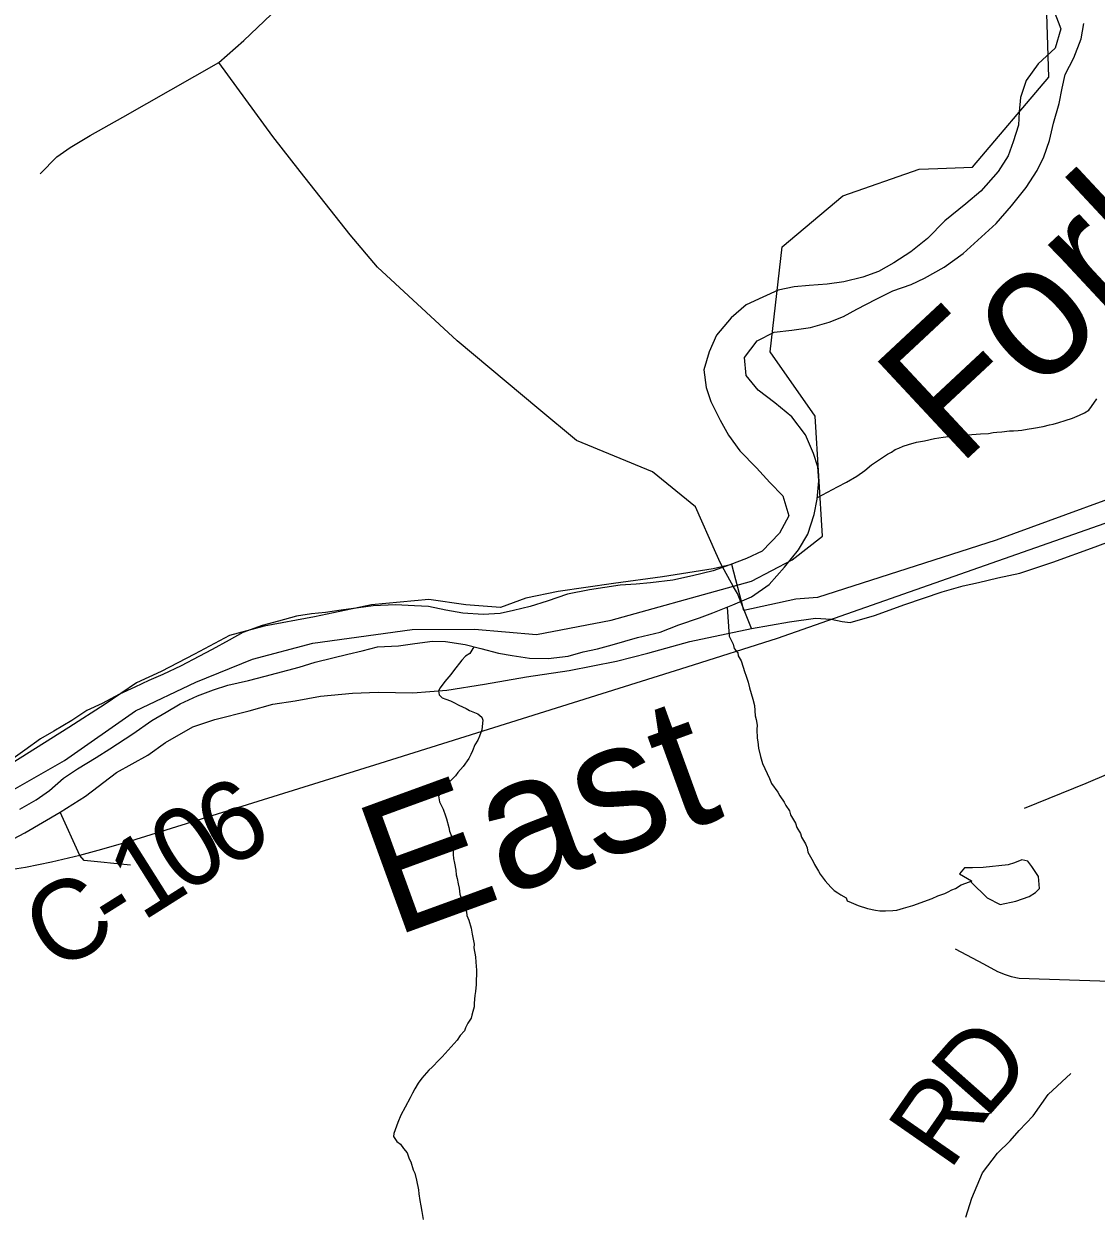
# Model space of a CAD drawing. Extents: x 0 to 34, y 0 to 22.
# Drawn here: x 6.1496 to 6.5335, y 18.3763 to 18.803 of the extents above; entities that cross this region are included whole.
import ezdxf

# ---------------------------------------------------------------- set-up
doc = ezdxf.new("R2010")
doc.units = 0
for name, color, linetype in [('GM_X_City_Street', 7, 'Continuous'), ('GM_X_Corporation', 7, 'Continuous'), ('GM_X_County_Road', 7, 'Continuous'), ('GM_X_County_Road_Text', 7, 'Continuous'), ('GM_X_Major_River', 7, 'Continuous'), ('GM_X_Major_River_Text', 7, 'Continuous'), ('GM_X_Minor_Lake', 7, 'Continuous'), ('GM_X_Minor_River', 7, 'Continuous'), ('GM_X_Rail_Line', 7, 'Continuous'), ('GM_X_Township', 7, 'Continuous'), ('GM_X_Township_Road', 7, 'Continuous'), ('GM_X_Township_Road_Text', 7, 'Continuous')]:
    doc.layers.add(name, color=color, linetype=linetype)

msp = doc.modelspace()

# ---------------------------------------------------------------- linework, layer by layer
at = {"layer": 'GM_X_City_Street'}
msp.add_lwpolyline([(6.15544, 18.74932), (6.16151, 18.7554), (6.16624, 18.75877), (6.17338, 18.76308), (6.18512, 18.76956), (6.21944, 18.7891)], dxfattribs=at)
at = {"layer": 'GM_X_Corporation'}
for points in [[(6.14063, 18.52601), (6.16415, 18.53935), (6.18957, 18.55715), (6.21118, 18.56732), (6.23152, 18.57559), (6.25312, 18.58131), (6.28865, 18.58623), (6.31096, 18.58639), (6.3332, 18.58449), (6.35989, 18.58957), (6.40364, 18.60179), (6.4101, 18.60356), (6.42472, 18.61118), (6.4355, 18.61968), (6.4329, 18.66259), (6.41682, 18.68566), (6.4211, 18.7232), (6.44286, 18.74144), (6.47015, 18.75104), (6.47689, 18.75126), (6.48931, 18.75167), (6.51663, 18.78387), (6.51458, 18.8485)], [(6.5611, 18.64133), (6.49767, 18.61824), (6.43381, 18.59772), (6.42603, 18.59709), (6.40738, 18.59304), (6.40313, 18.60945), (6.39637, 18.6079), (6.3783, 18.60505), (6.3607, 18.60268), (6.34097, 18.59987), (6.32932, 18.59744), (6.32028, 18.59411), (6.30792, 18.59506), (6.2946, 18.59697), (6.27416, 18.59506), (6.25371, 18.59078), (6.23564, 18.58745), (6.22327, 18.58413), (6.21071, 18.57738), (6.19878, 18.57116), (6.18999, 18.56712), (6.17881, 18.55951), (6.16573, 18.55118), (6.14505, 18.53811)]]:
    msp.add_lwpolyline(points, dxfattribs=at)
at = {"layer": 'GM_X_County_Road'}
for points in [[(6.33404, 18.66506), (6.30473, 18.68949), (6.27628, 18.7159), (6.26647, 18.7275), (6.24855, 18.75009), (6.23876, 18.76263), (6.21944, 18.7891), (6.22844, 18.797), (6.25779, 18.82504)], [(6.39742, 18.61361), (6.39013, 18.63016), (6.37464, 18.64263), (6.34754, 18.65381), (6.33404, 18.66506)], [(6.41016, 18.58664), (6.42376, 18.58898), (6.43302, 18.59026), (6.43862, 18.5899), (6.44255, 18.58905), (6.44546, 18.5887), (6.4542, 18.59119), (6.46507, 18.59513), (6.47843, 18.59975), (6.48588, 18.60181), (6.49135, 18.60309), (6.49838, 18.60472), (6.50626, 18.60643), (6.51807, 18.61036), (6.53322, 18.61584), (6.56259, 18.62681)], [(6.40444, 18.6003), (6.40375, 18.60153), (6.39904, 18.60994), (6.39742, 18.61361)], [(6.41016, 18.58664), (6.40513, 18.59908), (6.40444, 18.6003)], [(6.13972, 18.50806), (6.15002, 18.51339), (6.16267, 18.5208), (6.1717, 18.52658), (6.18282, 18.53505), (6.19402, 18.54122), (6.20034, 18.54574), (6.2101, 18.55134), (6.21805, 18.55405), (6.23034, 18.55712), (6.23883, 18.55947), (6.24679, 18.56073), (6.25585, 18.56236), (6.26724, 18.56346), (6.27653, 18.56384), (6.28892, 18.56353), (6.30108, 18.56454), (6.3146, 18.56671), (6.32961, 18.56928), (6.34488, 18.5716), (6.36179, 18.57492), (6.37298, 18.57772), (6.38806, 18.58187), (6.41016, 18.58664)]]:
    msp.add_lwpolyline(points, dxfattribs=at)
at = {"layer": 'GM_X_Major_River'}
for points in [[(6.51836, 18.80776), (6.52087, 18.80124), (6.51882, 18.79425), (6.51282, 18.78867), (6.50851, 18.78267), (6.50648, 18.77663), (6.50599, 18.7715), (6.50569, 18.76676), (6.50385, 18.76071), (6.50204, 18.7558), (6.4985, 18.75017), (6.49227, 18.74307), (6.48685, 18.73862), (6.47932, 18.7325), (6.47311, 18.72616), (6.46712, 18.72134), (6.46115, 18.71747), (6.45557, 18.71435), (6.45003, 18.71237), (6.44315, 18.71061), (6.43725, 18.70978), (6.43079, 18.70934), (6.42546, 18.70888), (6.41974, 18.70767), (6.41418, 18.70512), (6.40824, 18.70239), (6.40282, 18.69775), (6.39756, 18.69158), (6.39496, 18.68555), (6.39311, 18.67912), (6.39393, 18.67283), (6.39553, 18.66785), (6.39898, 18.66113), (6.4019, 18.65574), (6.40596, 18.65014), (6.4119, 18.64413), (6.41672, 18.63889), (6.42136, 18.63404), (6.42348, 18.62696), (6.42012, 18.62076), (6.4139, 18.61423), (6.40834, 18.61168), (6.40241, 18.60933), (6.39647, 18.60717), (6.38903, 18.60542), (6.38198, 18.60386), (6.37398, 18.60288), (6.36885, 18.60241), (6.36315, 18.60215), (6.3521, 18.60048)], [(6.51823, 18.76745), (6.52029, 18.77444), (6.52136, 18.77993), (6.52241, 18.78486), (6.52558, 18.79088), (6.5282, 18.79767), (6.52908, 18.80317)], [(6.14823, 18.52194), (6.154, 18.52525), (6.15882, 18.52857), (6.16385, 18.53303), (6.16886, 18.53635), (6.17559, 18.5404), (6.18041, 18.54353), (6.18868, 18.54888), (6.19543, 18.55368), (6.20062, 18.55662), (6.20562, 18.55956), (6.21176, 18.56248), (6.2175, 18.56464), (6.22266, 18.56625), (6.2301, 18.56799), (6.23602, 18.56958), (6.24824, 18.57275), (6.25397, 18.57454), (6.26027, 18.57612), (6.26561, 18.57734), (6.27076, 18.57857), (6.2763, 18.57998), (6.28371, 18.58039), (6.28961, 18.58122), (6.29589, 18.58204), (6.30064, 18.58195), (6.30764, 18.58085), (6.3133, 18.5794), (6.31953, 18.57775), (6.32444, 18.57689), (6.33069, 18.576), (6.33733, 18.57587), (6.34456, 18.57667), (6.34991, 18.57827), (6.35506, 18.57931), (6.36021, 18.58072), (6.36938, 18.58339), (6.37739, 18.58531), (6.38409, 18.58784), (6.39155, 18.59035), (6.39634, 18.59215), (6.40342, 18.59505), (6.41013, 18.59795), (6.41649, 18.60238), (6.42194, 18.60855), (6.42701, 18.61472), (6.43036, 18.62036), (6.4326, 18.62735), (6.43367, 18.63284), (6.4342, 18.63948), (6.43392, 18.64443), (6.43232, 18.64922), (6.42943, 18.65593), (6.42463, 18.66231), (6.41848, 18.66738), (6.41251, 18.67188), (6.40825, 18.6771), (6.40764, 18.68358), (6.41214, 18.68957), (6.41828, 18.69268), (6.42455, 18.69331), (6.43122, 18.69431), (6.43791, 18.69627), (6.44307, 18.69825), (6.44788, 18.70082), (6.45479, 18.70448), (6.46074, 18.7074), (6.46724, 18.70974), (6.47203, 18.71192), (6.47915, 18.71596), (6.48589, 18.72076), (6.49248, 18.72671), (6.49771, 18.73155), (6.50316, 18.7379), (6.50843, 18.74445), (6.51236, 18.75045), (6.51474, 18.75535), (6.51677, 18.7612), (6.51823, 18.76745)], [(6.3521, 18.60048), (6.34429, 18.59892), (6.33702, 18.59641), (6.3309, 18.59445), (6.32499, 18.59305), (6.32022, 18.592), (6.31413, 18.59156), (6.30674, 18.59209), (6.30069, 18.59317), (6.29446, 18.59443), (6.28953, 18.59473), (6.2827, 18.59506), (6.27472, 18.59465), (6.26939, 18.594), (6.2633, 18.59317), (6.25759, 18.59234), (6.25264, 18.59187), (6.24731, 18.59103), (6.24082, 18.58926), (6.2349, 18.58767), (6.22801, 18.58515), (6.2232, 18.5824), (6.21706, 18.5791), (6.21226, 18.57654), (6.20592, 18.57324), (6.1994, 18.57015), (6.19442, 18.56797), (6.18943, 18.5656), (6.18387, 18.56305), (6.17772, 18.55975), (6.17216, 18.5572), (6.16677, 18.5537), (6.16042, 18.54984), (6.15562, 18.54708), (6.15002, 18.54302), (6.14501, 18.53951)]]:
    msp.add_lwpolyline(points, dxfattribs=at)
at = {"layer": 'GM_X_Minor_Lake'}
msp.add_lwpolyline([(6.48886, 18.49632), (6.48874, 18.4958), (6.49451, 18.49017), (6.49921, 18.48779), (6.50475, 18.48901), (6.50953, 18.49062), (6.51184, 18.49209), (6.5132, 18.49358), (6.51291, 18.49777), (6.51052, 18.50143), (6.50904, 18.50336), (6.50695, 18.50378), (6.50427, 18.5027), (6.50198, 18.50199)], dxfattribs=at)
at = {"layer": 'GM_X_Minor_River'}
for points in [[(6.43372, 18.63349), (6.4409, 18.63731), (6.44417, 18.63893), (6.44783, 18.64111), (6.45073, 18.64313), (6.45306, 18.64515), (6.45557, 18.64679), (6.45886, 18.64898), (6.46021, 18.64971), (6.46156, 18.65062), (6.4629, 18.65115), (6.46444, 18.65187), (6.46635, 18.65239), (6.46922, 18.65327), (6.47208, 18.65376), (6.47571, 18.65461), (6.47876, 18.6551), (6.48162, 18.65541), (6.48276, 18.65557), (6.48619, 18.65586), (6.48904, 18.65597), (6.49209, 18.65627), (6.49494, 18.65639), (6.49666, 18.65672), (6.49799, 18.65688), (6.4997, 18.65702), (6.50256, 18.65732), (6.50389, 18.65729), (6.5056, 18.65743), (6.50693, 18.65759), (6.50884, 18.65792), (6.51113, 18.65824), (6.51456, 18.65891), (6.51686, 18.65942), (6.51819, 18.65976), (6.52011, 18.66028), (6.5224, 18.66098), (6.52508, 18.66186), (6.52758, 18.66293), (6.52931, 18.66383), (6.53086, 18.66474), (6.53184, 18.66604), (6.53381, 18.66884)], [(6.40143, 18.59423), (6.40213, 18.58388), (6.40357, 18.581), (6.40392, 18.57947), (6.40521, 18.57792), (6.40537, 18.57678), (6.40646, 18.57504), (6.40716, 18.57275), (6.40769, 18.57122), (6.40822, 18.5695), (6.40893, 18.56739), (6.40944, 18.56529), (6.41067, 18.56127), (6.41118, 18.55899), (6.41147, 18.55537), (6.41181, 18.55404), (6.41214, 18.55194), (6.4121, 18.55042), (6.41222, 18.54739), (6.41237, 18.54605), (6.41269, 18.54377), (6.41338, 18.54072), (6.41407, 18.53823), (6.41659, 18.53285), (6.41731, 18.53113), (6.41951, 18.52804), (6.42024, 18.52669), (6.42189, 18.52437), (6.42243, 18.52322), (6.42371, 18.52129), (6.42405, 18.51995), (6.42587, 18.51687), (6.4264, 18.51534), (6.42768, 18.51322), (6.42803, 18.51188), (6.42949, 18.50956), (6.43002, 18.50803), (6.43036, 18.50651), (6.43217, 18.50323), (6.43271, 18.50208), (6.43417, 18.49977), (6.43472, 18.49861), (6.43656, 18.49629), (6.43858, 18.49396), (6.43969, 18.49279), (6.441, 18.492), (6.44212, 18.49121), (6.444, 18.49022), (6.44435, 18.48907), (6.44585, 18.48846), (6.44829, 18.48745), (6.45169, 18.48641), (6.45452, 18.48577), (6.45603, 18.48554), (6.45812, 18.48548), (6.46078, 18.4856), (6.46211, 18.48576), (6.4646, 18.48645), (6.46786, 18.4875), (6.47476, 18.48998), (6.47687, 18.49087), (6.47936, 18.49176), (6.48051, 18.49229), (6.48186, 18.49302), (6.4832, 18.49355), (6.48514, 18.49483), (6.4882, 18.49589), (6.48886, 18.49632)], [(6.3107, 18.58007), (6.30929, 18.57758), (6.30775, 18.57668), (6.30638, 18.57519), (6.30344, 18.57148), (6.30246, 18.57017), (6.3003, 18.56757), (6.29873, 18.56534), (6.29813, 18.56422), (6.29828, 18.56289), (6.29939, 18.56172), (6.30071, 18.5613), (6.30241, 18.56069), (6.30353, 18.56009), (6.3054, 18.55909), (6.30803, 18.55789), (6.30916, 18.55729), (6.31216, 18.55607), (6.31365, 18.5549), (6.314, 18.55375), (6.31354, 18.55035), (6.31272, 18.54809), (6.31211, 18.54659), (6.31112, 18.54491), (6.31031, 18.54284), (6.30971, 18.54153), (6.30891, 18.54003), (6.30694, 18.53724), (6.30498, 18.53501), (6.30419, 18.5339), (6.30146, 18.53112), (6.2999, 18.52927), (6.29891, 18.52777), (6.29812, 18.52666), (6.29845, 18.52456), (6.29971, 18.52187), (6.3006, 18.51957), (6.30095, 18.51843), (6.30182, 18.51537), (6.30198, 18.51404), (6.3027, 18.51231), (6.30283, 18.51003), (6.30298, 18.5087), (6.30332, 18.50717), (6.30329, 18.50566), (6.30344, 18.50432), (6.30378, 18.50261), (6.30429, 18.50013), (6.30443, 18.49842), (6.30478, 18.49708), (6.30511, 18.49517), (6.30545, 18.49365), (6.30578, 18.49155), (6.30613, 18.49041), (6.30738, 18.48734), (6.30808, 18.48523), (6.30824, 18.4839), (6.30896, 18.48217), (6.30983, 18.47931), (6.31016, 18.47721), (6.31083, 18.47359), (6.31079, 18.47226), (6.31128, 18.46902), (6.31142, 18.46712), (6.31173, 18.46427), (6.3116, 18.45915), (6.31135, 18.45669), (6.31112, 18.45518), (6.31086, 18.45253), (6.31083, 18.4512), (6.3104, 18.44951), (6.30999, 18.44819), (6.30977, 18.44706), (6.30859, 18.44538), (6.30779, 18.4437), (6.30738, 18.44257), (6.30582, 18.4409), (6.30482, 18.43922), (6.29936, 18.43329), (6.29838, 18.43218), (6.29584, 18.42959), (6.29468, 18.42848), (6.29214, 18.4257), (6.29076, 18.42384), (6.28957, 18.42179), (6.28877, 18.42029), (6.28797, 18.4186), (6.28617, 18.41524), (6.28458, 18.41243), (6.28357, 18.4098), (6.28214, 18.40586), (6.28192, 18.40472), (6.2832, 18.40298), (6.28451, 18.402), (6.28561, 18.40045), (6.2869, 18.3989), (6.2876, 18.3968), (6.28814, 18.39565), (6.28902, 18.39278), (6.28956, 18.39163), (6.29026, 18.38914)], [(6.50204, 18.502), (6.49303, 18.50103), (6.48923, 18.50092), (6.48638, 18.50098), (6.48462, 18.49873), (6.48886, 18.49632)], [(6.29026, 18.38914), (6.29093, 18.38571), (6.29108, 18.38419), (6.2914, 18.3819), (6.29173, 18.38), (6.29206, 18.3779), (6.29256, 18.37504)]]:
    msp.add_lwpolyline(points, dxfattribs=at)
at = {"layer": 'GM_X_Rail_Line'}
msp.add_lwpolyline([(6.13301, 18.49856), (6.15021, 18.50122), (6.15949, 18.50304), (6.16972, 18.50542), (6.17757, 18.50756), (6.18796, 18.51058), (6.27716, 18.53841), (6.3871, 18.57288), (6.41945, 18.58314), (6.5728, 18.6369)], dxfattribs=at)
at = {"layer": 'GM_X_Township'}
msp.add_lwpolyline([(6.14063, 18.52601), (6.16415, 18.53935), (6.18957, 18.55715), (6.21118, 18.56732), (6.23152, 18.57559), (6.25312, 18.58131), (6.28865, 18.58623), (6.31096, 18.58639), (6.3332, 18.58449), (6.35989, 18.58957), (6.40364, 18.60179), (6.4101, 18.60356), (6.42472, 18.61118), (6.4355, 18.61968), (6.4329, 18.66259), (6.41682, 18.68566), (6.4211, 18.7232), (6.44286, 18.74144), (6.47015, 18.75104), (6.47689, 18.75126), (6.48931, 18.75167), (6.51663, 18.78387), (6.51458, 18.8485)], dxfattribs=at)
at = {"layer": 'GM_X_Township_Road'}
for points in [[(6.53797, 18.53456), (6.52987, 18.53111), (6.50776, 18.52216)], [(6.1878, 18.50192), (6.17128, 18.50351), (6.16973, 18.50537), (6.16267, 18.5208)], [(6.48301, 18.47188), (6.49316, 18.46656), (6.49824, 18.46377), (6.50096, 18.46272), (6.50313, 18.46204), (6.50591, 18.46142), (6.5384, 18.4603), (6.56236, 18.45964), (6.57157, 18.4593)], [(6.48692, 18.37585), (6.48897, 18.3827), (6.49289, 18.39179), (6.49817, 18.39874), (6.50276, 18.40323), (6.50599, 18.40695), (6.51098, 18.41213), (6.51636, 18.41976), (6.52447, 18.42729)]]:
    msp.add_lwpolyline(points, dxfattribs=at)

# ---------------------------------------------------------------- texts
at = {"layer": 'GM_X_County_Road_Text'}
for s, rotation, p in [('6', 28.0058, (6.22117, 18.50003)), ('0', 32.5167, (6.20692, 18.49093)), ('1', 32.2639, (6.19201, 18.48151)), ('C', 29.1789, (6.16032, 18.46309)), ('-', 32.0718, (6.18204, 18.47526))]:
    msp.add_text(s, height=0.02841, rotation=rotation, dxfattribs=at).set_placement(p)
at = {"layer": 'GM_X_Major_River_Text'}
for s, height, rotation, p in [('Fork', 0.047352, 43.0031, (6.48386, 18.64397)), ('East', 0.04735, 20.0034, (6.28193, 18.47605))]:
    msp.add_text(s, height=height, rotation=rotation, dxfattribs=at).set_placement(p)
at = {"layer": 'GM_X_Township_Road_Text'}
for s, rotation, p in [('D', 48.5002, (6.49375, 18.4105)), ('R', 55.1992, (6.48098, 18.39203))]:
    msp.add_text(s, height=0.02841, rotation=rotation, dxfattribs=at).set_placement(p)

doc.saveas('drawing.dxf')
